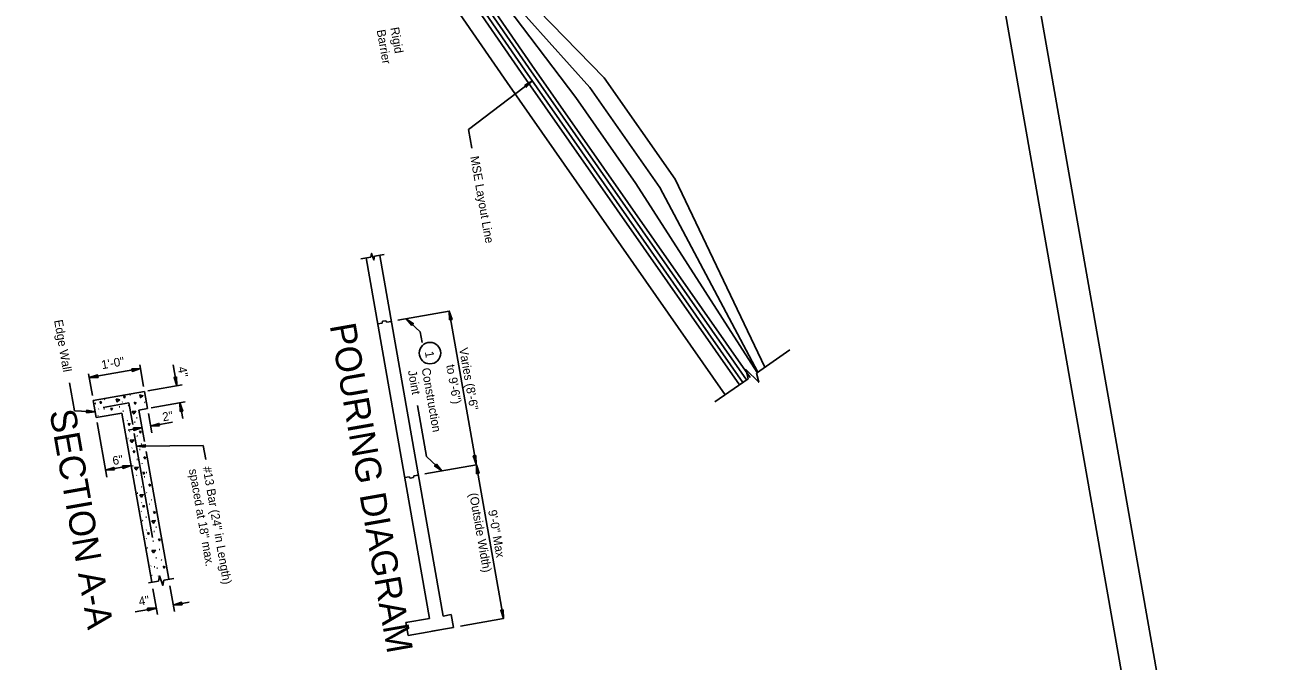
# Model space of a CAD drawing. Extents: x 1971280 to 1971503, y 796034 to 796348.
# Drawn here: x 1971359.4 to 1971502.9, y 796139.3 to 796212.6 of the extents above; entities that cross this region are included whole.
import ezdxf

# ---------------------------------------------------------------- set-up
doc = ezdxf.new("R2010")
doc.units = 0
for name, color, linetype in [('BR_AUTO DIMENSION', 7, 'Continuous'), ('BR_BORDER LINES', 7, 'Continuous'), ('BR_CENTER LINES', 7, 'Continuous'), ('BR_CONCRETE', 7, 'Continuous'), ('BR_REBAR', 7, 'Continuous'), ('BR_TABLE LINES', 7, 'Continuous'), ('BR_TEXT', 7, 'Continuous'), ('Level 31', 7, 'Continuous')]:
    doc.layers.add(name, color=color, linetype=linetype)

msp = doc.modelspace()

# ---------------------------------------------------------------- linework, layer by layer
at = {"layer": 'BR_AUTO DIMENSION'}
for p, q in [((1971417.92, 796206.17), (1971410.57, 796200.57)), ((1971410.57, 796200.57), (1971410.95, 796198.43)), ((1971402.41, 796178.58), (1971408.34, 796179.63)), ((1971408.34, 796179.63), (1971414.58, 796144.18)), ((1971403.38, 796178.75), (1971404.99, 796177.24)), ((1971404.99, 796177.24), (1971405.2, 796176.01)), ((1971447.58, 796175.18), (1971443.74, 796172.49)), ((1971366.75, 796172.41), (1971367.19, 796169.89)), ((1971366.83, 796171.96), (1971372.74, 796173)), ((1971372.66, 796173.45), (1971373.1, 796170.94)), ((1971376.5, 796173.44), (1971376.93, 796171.03)), ((1971364.54, 796171.38), (1971365.11, 796168.14)), ((1971373.6, 796170.44), (1971377.54, 796171.14)), ((1971442.79, 796171.83), (1971438.97, 796169.16)), ((1971367.52, 796168.01), (1971365.11, 796168.14)), ((1971373.95, 796168.47), (1971377.89, 796169.17)), ((1971377.28, 796169.06), (1971377.6, 796167.24)), ((1971404.66, 796168.76), (1971405.7, 796162.88)), ((1971367.74, 796166.78), (1971368.85, 796160.5)), ((1971373.65, 796167.82), (1971374.04, 796165.59)), ((1971373.9, 796166.37), (1971376.43, 796166.81)), ((1971371.3, 796165.91), (1971372.92, 796166.2)), ((1971372.28, 796164.07), (1971379.97, 796164.15)), ((1971379.97, 796164.15), (1971380.26, 796162.51)), ((1971407.48, 796161.2), (1971405.7, 796162.88)), ((1971368.71, 796161.3), (1971371.66, 796161.82)), ((1971405.53, 796160.86), (1971411.46, 796161.9)), ((1971376.65, 796145.01), (1971376.13, 796147.96)), ((1971374.68, 796144.67), (1971374.16, 796147.62)), ((1971372.11, 796144.97), (1971374.55, 796145.4)), ((1971376.52, 796145.74), (1971378.34, 796146.06)), ((1971409.61, 796143.31), (1971414.58, 796144.18))]:
    msp.add_line(p, q, dxfattribs=at)
for points in [[(1971417.03, 796205.68), (1971417.92, 796206.17), (1971417.21, 796205.44)], [(1971408.36, 796178.62), (1971408.34, 796179.63), (1971408.66, 796178.67)], [(1971404, 796177.96), (1971403.38, 796178.75), (1971404.21, 796178.18)], [(1971367.84, 796171.98), (1971366.83, 796171.96), (1971367.79, 796172.28)], [(1971371.73, 796172.97), (1971372.74, 796173), (1971371.78, 796172.68)], [(1971376.9, 796172.04), (1971376.93, 796171.03), (1971376.61, 796171.99)], [(1971366.52, 796167.91), (1971367.52, 796168.01), (1971366.53, 796168.21)], [(1971377.3, 796168.05), (1971377.28, 796169.06), (1971377.6, 796168.1)], [(1971374.91, 796166.39), (1971373.9, 796166.37), (1971374.86, 796166.69)], [(1971371.91, 796166.17), (1971372.92, 796166.2), (1971371.96, 796165.87)], [(1971373.28, 796163.93), (1971372.28, 796164.07), (1971373.28, 796164.23)], [(1971411.4, 796163), (1971411.42, 796161.98), (1971411.1, 796162.94)], [(1971369.72, 796161.33), (1971368.71, 796161.3), (1971369.66, 796161.62)], [(1971370.65, 796161.79), (1971371.66, 796161.82), (1971370.7, 796161.5)], [(1971406.86, 796162), (1971407.48, 796161.2), (1971406.65, 796161.78)], [(1971411.48, 796160.89), (1971411.46, 796161.9), (1971411.78, 796160.95)], [(1971373.54, 796145.37), (1971374.55, 796145.4), (1971373.59, 796145.08)], [(1971377.53, 796145.77), (1971376.52, 796145.74), (1971377.48, 796146.06)], [(1971414.55, 796145.19), (1971414.58, 796144.18), (1971414.26, 796145.14)]]:
    msp.add_lwpolyline(points, close=True, dxfattribs=at)
msp.add_lwpolyline([(1971443.74, 796172.49), (1971444.01, 796171.43), (1971442.52, 796172.89), (1971442.79, 796171.83)], dxfattribs=at)
at = {"layer": 'BR_BORDER LINES'}
msp.add_line((1971498.22, 796067.69), (1971451.51, 796332.94), dxfattribs=at)
at = {"layer": 'BR_CENTER LINES'}
for points in [[(1971399.3, 796185.87), (1971399.38, 796186.28), (1971399.65, 796185.54), (1971399.73, 796185.95)], [(1971374.8, 796148.5), (1971374.91, 796149.11), (1971375.33, 796148.01), (1971375.44, 796148.61)]]:
    msp.add_lwpolyline(points, dxfattribs=at)
at = {"layer": 'BR_CONCRETE'}
for p, q in [((1971409.49, 796223.66), (1971426.19, 796206.54)), ((1971410.23, 796221.36), (1971424.55, 796205.4)), ((1971412.04, 796218.64), (1971422.92, 796204.25)), ((1971443.85, 796172.57), (1971429.84, 796194.34)), ((1971443.89, 796172.59), (1971432.6, 796193.88)), ((1971444.73, 796173.18), (1971434.37, 796194.84)), ((1971398.74, 796185.77), (1971406.06, 796144.2)), ((1971400.31, 796186.05), (1971407.63, 796144.48)), ((1971400.58, 796178.26), (1971400.08, 796178.17)), ((1971400.64, 796178.46), (1971400.58, 796178.26)), ((1971401.01, 796178.53), (1971400.64, 796178.46)), ((1971401.14, 796178.36), (1971401.01, 796178.53)), ((1971401.65, 796178.45), (1971401.14, 796178.36)), ((1971373.2, 796170.37), (1971367.29, 796169.33)), ((1971367.29, 796169.33), (1971367.64, 796167.36)), ((1971373.2, 796170.37), (1971373.55, 796168.4)), ((1971370.59, 796167.88), (1971367.64, 796167.36)), ((1971370.59, 796167.88), (1971374.03, 796148.37)), ((1971373.55, 796168.4), (1971372.56, 796168.23)), ((1971372.56, 796168.23), (1971373.2, 796164.6)), ((1971373.4, 796163.46), (1971376, 796148.71)), ((1971404.77, 796160.73), (1971404.26, 796160.64)), ((1971403.71, 796160.54), (1971403.2, 796160.45)), ((1971403.83, 796160.37), (1971403.71, 796160.54)), ((1971404.2, 796160.44), (1971403.83, 796160.37)), ((1971404.26, 796160.64), (1971404.2, 796160.44)), ((1971406.06, 796144.2), (1971403.32, 796143.72)), ((1971403.32, 796143.72), (1971403.58, 796142.24)), ((1971408.55, 796144.64), (1971407.63, 796144.48)), ((1971408.55, 796144.64), (1971408.81, 796143.17)), ((1971405.8, 796142.63), (1971403.58, 796142.24)), ((1971405.8, 796142.63), (1971407.89, 796143)), ((1971408.81, 796143.17), (1971406.32, 796142.73))]:
    msp.add_line(p, q, dxfattribs=at)
for points in [[(1971359.85, 796292.79), (1971360.47, 796291.64), (1971364.52, 796285.01), (1971365.78, 796283.1), (1971380.75, 796260.96), (1971398.02, 796235.9), (1971417.46, 796207.7), (1971442.6, 796171.7)], [(1971359.41, 796292.55), (1971360.04, 796291.39), (1971364.1, 796284.75), (1971365.36, 796282.83), (1971380.34, 796260.67), (1971397.61, 796235.61), (1971417.05, 796207.42), (1971442.19, 796171.41)], [(1971401.59, 796225.44), (1971414.99, 796205.99), (1971440.14, 796169.98)], [(1971403.79, 796225.77), (1971416.64, 796207.13), (1971441.78, 796171.12)], [(1971405.44, 796226.02), (1971417.87, 796207.99), (1971443.01, 796171.98)], [(1971424.55, 796205.4), (1971432.6, 796193.88)], [(1971426.19, 796206.54), (1971434.37, 796194.84)], [(1971422.92, 796204.25), (1971429.84, 796194.34)]]:
    msp.add_lwpolyline(points, dxfattribs=at)
at = {"layer": 'BR_REBAR'}
for p, q in [((1971371.4, 796169.04), (1971368.45, 796168.52)), ((1971371.4, 796169.04), (1971371.84, 796166.56)), ((1971372.02, 796165.51), (1971374.13, 796153.53))]:
    msp.add_line(p, q, dxfattribs=at)
at = {"layer": 'BR_TABLE LINES'}
for p, q in [((1971399.3, 796185.87), (1971398.15, 796185.67)), ((1971400.82, 796186.14), (1971399.73, 796185.95)), ((1971373.64, 796148.3), (1971374.8, 796148.5)), ((1971375.44, 796148.61), (1971376.59, 796148.82))]:
    msp.add_line(p, q, dxfattribs=at)
at = {"layer": 'BR_TEXT'}
for p, q in [((1971368.6, 796169.48), (1971368.67, 796169.46)), ((1971371.5, 796169.99), (1971371.57, 796169.97)), ((1971367.92, 796168.38), (1971367.89, 796168.34)), ((1971368.5, 796168.36), (1971368.57, 796168.35)), ((1971370.29, 796168.61), (1971370.36, 796168.59)), ((1971370.65, 796169.18), (1971370.61, 796169.15)), ((1971370.7, 796168.09), (1971370.77, 796168.08)), ((1971371.31, 796168.78), (1971371.38, 796168.76)), ((1971373.19, 796169.12), (1971373.26, 796169.1)), ((1971367.81, 796167.58), (1971367.87, 796167.57)), ((1971370.75, 796166.98), (1971370.81, 796166.96)), ((1971371.22, 796167.01), (1971371.18, 796166.97)), ((1971372.05, 796166.84), (1971372.12, 796166.82)), ((1971372.35, 796167.34), (1971372.29, 796167.32)), ((1971371.49, 796165.74), (1971371.45, 796165.7)), ((1971372.32, 796165.24), (1971372.39, 796165.22)), ((1971371.26, 796164.94), (1971371.32, 796164.93)), ((1971371.31, 796163.83), (1971371.37, 796163.81)), ((1971371.77, 796163.86), (1971371.73, 796163.82)), ((1971372.61, 796163.69), (1971372.68, 796163.67)), ((1971372.88, 796164.32), (1971372.82, 796164.3)), ((1971372.32, 796162.54), (1971372.39, 796162.52)), ((1971372.94, 796162.12), (1971372.91, 796162.08)), ((1971371.81, 796161.79), (1971371.88, 796161.78)), ((1971371.86, 796160.68), (1971371.92, 796160.66)), ((1971372.33, 796160.7), (1971372.29, 796160.67)), ((1971373.46, 796161.04), (1971373.4, 796161.02)), ((1971372.84, 796159.38), (1971372.9, 796159.36)), ((1971373.16, 796160.54), (1971373.23, 796160.52)), ((1971372.36, 796158.64), (1971372.43, 796158.63)), ((1971373.47, 796158.72), (1971373.43, 796158.69)), ((1971374.01, 796157.89), (1971373.95, 796157.87)), ((1971372.42, 796157.52), (1971372.48, 796157.51)), ((1971372.87, 796156.58), (1971372.83, 796156.54)), ((1971372.88, 796157.55), (1971372.84, 796157.52)), ((1971373.72, 796157.38), (1971373.79, 796157.37)), ((1971372.92, 796155.49), (1971372.99, 796155.47)), ((1971373.35, 796155.88), (1971373.42, 796155.87)), ((1971372.97, 796154.37), (1971373.03, 796154.36)), ((1971373.44, 796154.4), (1971373.4, 796154.37)), ((1971374.27, 796154.23), (1971374.34, 796154.22)), ((1971374.57, 796154.74), (1971374.51, 796154.72)), ((1971373.42, 796153.43), (1971373.39, 796153.39)), ((1971373.47, 796152.34), (1971373.54, 796152.32)), ((1971374.17, 796153.12), (1971374.24, 796153.1)), ((1971374.9, 796152.16), (1971374.97, 796152.15)), ((1971374.51, 796151.19), (1971374.58, 796151.18)), ((1971375.12, 796150.94), (1971375.19, 796150.92)), ((1971373.98, 796150.28), (1971373.94, 796150.24)), ((1971374.03, 796149.19), (1971374.1, 796149.17)), ((1971374.32, 796150.16), (1971374.38, 796150.14)), ((1971374.63, 796149.99), (1971374.7, 796149.98))]:
    msp.add_line(p, q, dxfattribs=at)
for points in [[(1971369.94, 796169.52), (1971370.33, 796169.39), (1971370.03, 796169.19), (1971369.94, 796169.51)], [(1971370.77, 796169.84), (1971370.96, 796169.79), (1971370.88, 796169.63), (1971370.77, 796169.84)], [(1971372.63, 796169.99), (1971373.02, 796169.87), (1971372.72, 796169.66), (1971372.64, 796169.99)], [(1971367.48, 796169.01), (1971367.54, 796168.99), (1971367.49, 796168.95)], [(1971368.04, 796169.21), (1971368.23, 796169.15), (1971368.15, 796168.99), (1971368.04, 796169.21)], [(1971369.3, 796168.45), (1971369.49, 796168.4), (1971369.41, 796168.24), (1971369.3, 796168.45)], [(1971371.77, 796168.06), (1971372.18, 796168.08), (1971371.96, 796167.78), (1971371.77, 796168.05)], [(1971372.02, 796169.13), (1971372.21, 796169.07), (1971372.13, 796168.91), (1971372.02, 796169.13)], [(1971371.32, 796166.69), (1971371.51, 796166.64), (1971371.43, 796166.48), (1971371.32, 796166.69)], [(1971370.88, 796166.24), (1971370.88, 796166.24), (1971370.88, 796166.24)], [(1971372.61, 796165.8), (1971372.8, 796165.74), (1971372.72, 796165.59), (1971372.61, 796165.8)], [(1971371.55, 796164.77), (1971371.96, 796164.79), (1971371.74, 796164.49), (1971371.55, 796164.77)], [(1971371.88, 796163.54), (1971372.07, 796163.49), (1971371.99, 796163.33), (1971371.88, 796163.54)], [(1971371.43, 796163.09), (1971371.44, 796163.09), (1971371.44, 796163.09)], [(1971373.13, 796162.82), (1971373.32, 796162.77), (1971373.24, 796162.61), (1971373.13, 796162.82)], [(1971372.06, 796161.62), (1971372.47, 796161.63), (1971372.25, 796161.33), (1971372.06, 796161.61)], [(1971373, 796161.06), (1971373.19, 796161.01), (1971373.11, 796160.85), (1971373, 796161.06)], [(1971371.99, 796159.94), (1971371.99, 796159.94), (1971371.99, 796159.94)], [(1971373.69, 796159.67), (1971373.88, 796159.62), (1971373.8, 796159.46), (1971373.69, 796159.67)], [(1971372.64, 796158.47), (1971373.05, 796158.48), (1971372.84, 796158.19), (1971372.64, 796158.46)], [(1971372.54, 796156.79), (1971372.55, 796156.79), (1971372.55, 796156.79)], [(1971372.99, 796157.24), (1971373.18, 796157.19), (1971373.1, 796157.03), (1971372.99, 796157.24)], [(1971374.24, 796156.52), (1971374.43, 796156.47), (1971374.35, 796156.31), (1971374.24, 796156.52)], [(1971374.03, 796155.47), (1971374.44, 796155.48), (1971374.22, 796155.18), (1971374.03, 796155.46)], [(1971373.35, 796153.68), (1971373.35, 796153.68), (1971373.35, 796153.68)], [(1971373.54, 796154.09), (1971373.73, 796154.04), (1971373.65, 796153.88), (1971373.54, 796154.09)], [(1971374.05, 796152.05), (1971374.46, 796152.06), (1971374.25, 796151.77), (1971374.05, 796152.04)], [(1971374.8, 796153.37), (1971374.99, 796153.32), (1971374.91, 796153.16), (1971374.8, 796153.37)], [(1971373.65, 796150.49), (1971373.66, 796150.49), (1971373.65, 796150.49)], [(1971375.35, 796150.22), (1971375.54, 796150.17), (1971375.46, 796150.01), (1971375.35, 796150.22)], [(1971374.81, 796149.11), (1971374.82, 796149.11)], [(1971374.82, 796149.09), (1971374.81, 796149.1)]]:
    msp.add_lwpolyline(points, dxfattribs=at)
msp.add_circle((1971406.11, 796174.79), 1.24, dxfattribs=at)
at = {"layer": 'Level 31'}
msp.add_line((1971502.85, 796064.44), (1971452.91, 796348.08), dxfattribs=at)

# ---------------------------------------------------------------- texts
at = {"layer": 'BR_TEXT'}
for s, height, rotation, p in [('Rigid', 1, 279.987, (1971401.54, 796212.28)), ('Barrier', 1, 279.987, (1971399.96, 796212)), ('MSE Layout Line', 0.9998, 279.987, (1971410.75, 796197.42)), ('Edge Wall', 1, 279.987, (1971362.77, 796178.55)), ('POURING DIAGRAM', 2.9993, 279.987, (1971394.54, 796177.99)), ('Varies (8\'-6"', 0.9998, 279.987, (1971409.47, 796175.32)), ('1\'-0"', 1, 9.987, (1971368.32, 796172.93)), ('1', 1, 279.987, (1971405.52, 796174.92)), ('4"', 1, 279.987, (1971377.03, 796173.14)), ('Joint', 1, 279.987, (1971403.56, 796172.73)), ('Construction', 0.9998, 279.987, (1971405.14, 796173.01)), ('to 9\'-6")', 1, 279.987, (1971407.98, 796173.38)), ('SECTION A-A', 2.9993, 279.987, (1971362.23, 796168.05)), ('2"', 1, 9.987, (1971375.35, 796166.92)), ('6"', 1, 9.987, (1971369.6, 796161.87)), ('spaced at 18" max.', 0.9998, 279.987, (1971378.31, 796161.36)), ('#13 Bar (24" in Length)', 0.9998, 279.987, (1971379.89, 796161.64)), ('(Outside Width)', 0.9998, 279.987, (1971410.63, 796158.59)), ('9\'-0" Max', 1, 279.987, (1971412.81, 796156.63)), ('4"', 1, 9.987, (1971372.62, 796145.66))]:
    msp.add_text(s, height=height, rotation=rotation, dxfattribs=at).set_placement(p)

doc.saveas('drawing.dxf')
